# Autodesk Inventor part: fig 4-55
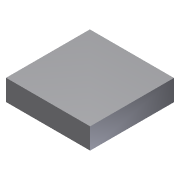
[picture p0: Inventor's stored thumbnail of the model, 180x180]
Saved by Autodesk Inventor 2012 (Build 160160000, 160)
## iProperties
Created: 2010-02
Part Number: fig 4-55
Document SubType Name: Modeling
Designer: CADSoft
Density: 1 g/cm^3
Material: Default
Author: CADSoft
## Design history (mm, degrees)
sketch "Sketch1"
  geometry: L1 (-20.026, 19.961)-(0, 19.961); L2 (0, 19.961)-(0, 0); L3 (0, 0)-(-20.026, 0); L4 (-20.026, 0)-(-20.026, 19.961)
  constraints: 8 end point
extrude "Extrusion1" new body sketch "Sketch1" distance "d0" = 5; taper "d1" = 0 deg
body "Solid1"
